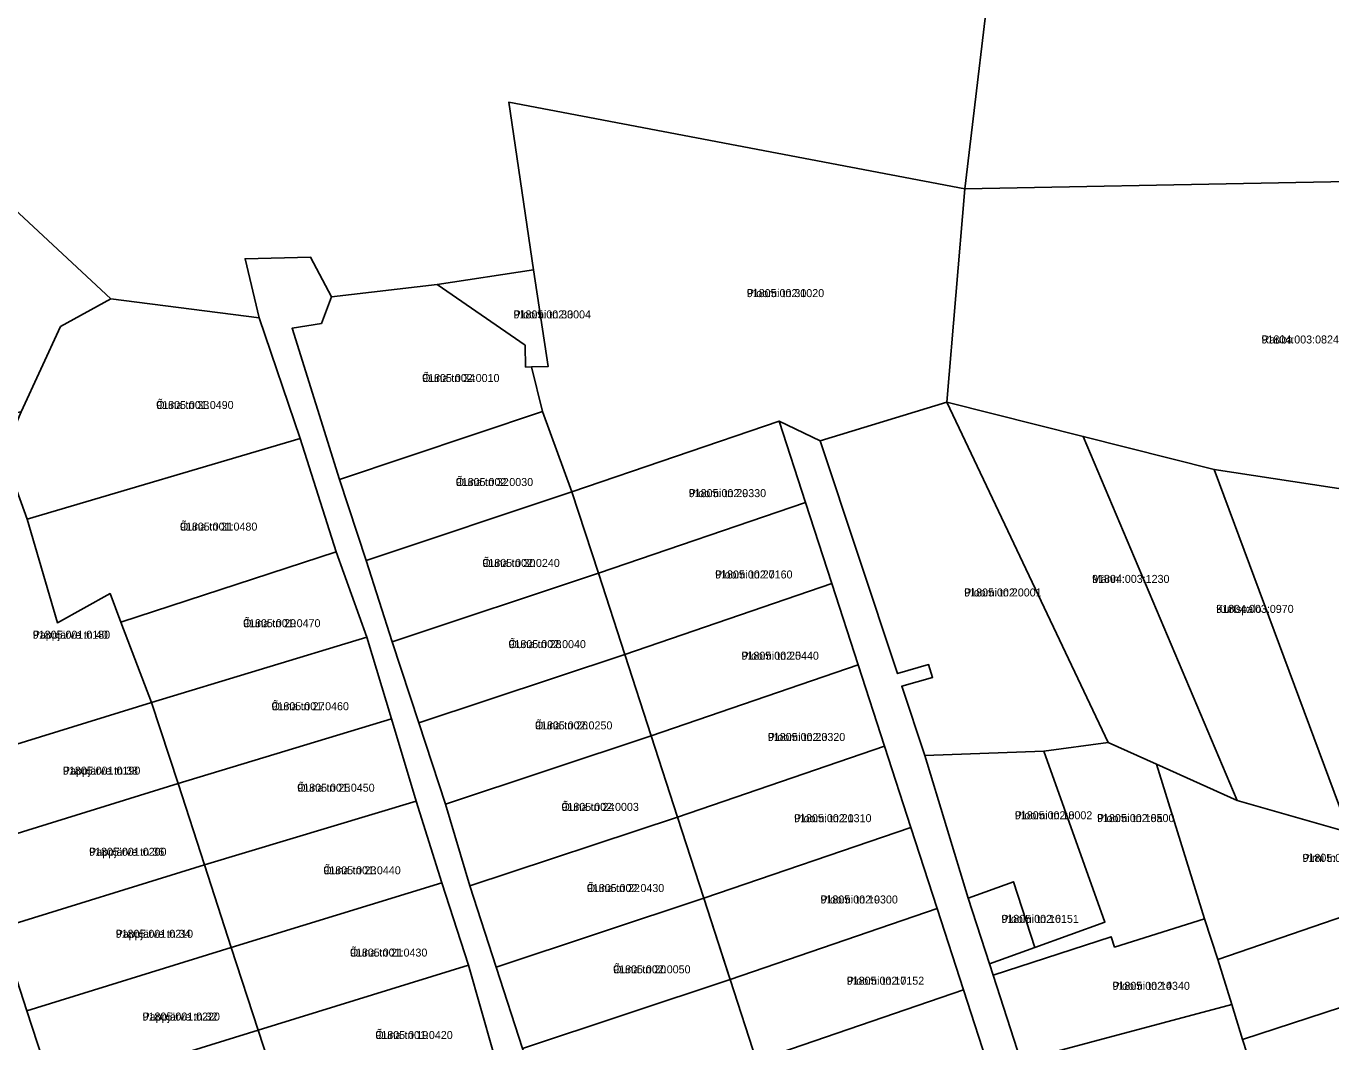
# Model space of a CAD drawing. Extents: x 655954 to 711923, y 6395079 to 6429745.
# Drawn here: x 680310.1 to 680554.7, y 6412480.8 to 6412671.1 of the extents above; entities that cross this region are included whole.
import ezdxf

# ---------------------------------------------------------------- set-up
doc = ezdxf.new("R2010")
doc.units = 0
for name, color, linetype in [('L_AADRESS', 7, 'Continuous'), ('PIIR', 7, 'Continuous'), ('TUNNUS', 7, 'Continuous')]:
    doc.layers.add(name, color=color, linetype=linetype)

msp = doc.modelspace()

# ---------------------------------------------------------------- linework, layer by layer
at = {"layer": 'PIIR'}
for points in [[(680073.18, 6412716.55), (679963.62, 6412773.02), (680013.99, 6412769.75), (680328.3, 6412722.25), (680332.79, 6412721.57), (680343.95, 6412719.89), (680491.74, 6412688.36), (680486.09, 6412640.6), (680400.58, 6412656.82), (680405.26, 6412625.45), (680387.19, 6412622.66), (680367.38, 6412620.4), (680363.46, 6412627.78), (680351.17, 6412627.52), (680353.8, 6412616.41), (680326.05, 6412620), (680257.17, 6412684.06), (680249.09, 6412691.57), (680191.97, 6412698), (680185.92, 6412698.62), (680079.1, 6412709.57)], [(680079.1, 6412709.57), (680185.92, 6412698.62), (680191.97, 6412698), (680249.09, 6412691.57), (680257.17, 6412684.06), (680326.05, 6412620), (680316.57, 6412614.8), (680309.19, 6412598.8), (680270.74, 6412592.3), (680233.25, 6412591.29), (680181.76, 6412579.27), (680138.22, 6412633.47), (680079.96, 6412707.89)], [(680491.74, 6412688.36), (680636.79, 6412656.6), (680647.63, 6412619.14), (680657.8, 6412581.77), (680595.75, 6412580.4), (680603.61, 6412642.87), (680486.09, 6412640.6)], [(680406.92, 6412598.88), (680404.87, 6412607.28), (680407.96, 6412607.31), (680405.26, 6412625.45), (680400.58, 6412656.82), (680486.09, 6412640.6), (680482.71, 6412600.64), (680458.97, 6412593.42), (680451.28, 6412597.1), (680412.42, 6412583.82)], [(680603.61, 6412642.87), (680595.75, 6412580.4), (680579.88, 6412580.85), (680532.8, 6412588.04), (680508.26, 6412594.22), (680482.71, 6412600.64), (680486.09, 6412640.6)], [(680387.19, 6412622.66), (680405.26, 6412625.45), (680407.96, 6412607.31), (680404.87, 6412607.28), (680403.74, 6412607.21), (680403.66, 6412611.31)], [(680359.99, 6412614.49), (680365.49, 6412615.4), (680367.38, 6412620.4), (680387.19, 6412622.66), (680403.66, 6412611.31), (680403.74, 6412607.21), (680404.87, 6412607.28), (680406.92, 6412598.88), (680368.89, 6412586.16)], [(680316.57, 6412614.8), (680326.05, 6412620), (680353.8, 6412616.41), (680361.49, 6412593.83), (680310.35, 6412578.72), (680305.94, 6412590.99), (680309.19, 6412598.8)], [(680482.71, 6412600.64), (680512.94, 6412536.85), (680500.84, 6412535.21), (680478.56, 6412534.41), (680474.24, 6412547.4), (680480.01, 6412549.05), (680479.27, 6412551.45), (680473.46, 6412549.78), (680458.97, 6412593.42)], [(680537.12, 6412526), (680521.99, 6412532.79), (680512.94, 6412536.85), (680482.71, 6412600.64), (680508.26, 6412594.22)], [(680373.9, 6412570.97), (680368.89, 6412586.16), (680406.92, 6412598.88), (680412.42, 6412583.82)], [(680451.28, 6412597.1), (680456.21, 6412581.86), (680417.39, 6412568.58), (680412.42, 6412583.82)], [(680325.88, 6412564.76), (680316, 6412559.3), (680310.35, 6412578.72), (680361.49, 6412593.83), (680368.25, 6412572.56), (680327.92, 6412559.41)], [(680558.11, 6412520.02), (680537.12, 6412526), (680508.26, 6412594.22), (680532.8, 6412588.04)], [(680305.94, 6412590.99), (680310.35, 6412578.72), (680316, 6412559.3), (680325.88, 6412564.76), (680327.92, 6412559.41), (680333.63, 6412544.38), (680295.42, 6412532.55), (680289.16, 6412551.54)], [(680579.88, 6412580.85), (680605.86, 6412505.28), (680576.12, 6412514.47), (680570.21, 6412516.3), (680558.11, 6412520.02), (680532.8, 6412588.04)], [(680378.76, 6412555.7), (680373.9, 6412570.97), (680412.42, 6412583.82), (680417.39, 6412568.58)], [(680456.21, 6412581.86), (680461.14, 6412566.64), (680422.35, 6412553.34), (680417.39, 6412568.58)], [(680368.25, 6412572.56), (680374, 6412556.63), (680333.63, 6412544.38), (680327.92, 6412559.41)], [(680378.76, 6412555.7), (680417.39, 6412568.58), (680422.35, 6412553.34), (680383.72, 6412540.52)], [(680461.14, 6412566.64), (680466.07, 6412551.41), (680427.29, 6412538.12), (680422.35, 6412553.34)], [(680374, 6412556.63), (680378.64, 6412541.32), (680338.67, 6412529.2), (680333.63, 6412544.38)], [(680383.72, 6412540.52), (680422.35, 6412553.34), (680427.29, 6412538.12), (680388.72, 6412525.31)], [(680466.07, 6412551.41), (680471.01, 6412536.19), (680432.22, 6412522.89), (680427.29, 6412538.12)], [(680333.63, 6412544.38), (680338.67, 6412529.2), (680300.34, 6412517.31), (680295.42, 6412532.55)], [(680378.64, 6412541.32), (680383.27, 6412525.9), (680343.58, 6412513.96), (680338.67, 6412529.2)], [(680427.29, 6412538.12), (680432.22, 6412522.89), (680393.31, 6412509.98), (680388.72, 6412525.31)], [(680471.01, 6412536.19), (680475.93, 6412520.96), (680437.15, 6412507.67), (680432.22, 6412522.89)], [(680490.68, 6412495.36), (680499.16, 6412498.42), (680512.32, 6412503.2), (680500.84, 6412535.21), (680512.94, 6412536.85), (680521.99, 6412532.79), (680530.99, 6412503.84), (680514.14, 6412498.52), (680513.5, 6412500.46), (680491.36, 6412493.27)], [(680478.56, 6412534.41), (680500.84, 6412535.21), (680512.32, 6412503.2), (680499.16, 6412498.42), (680495.17, 6412510.78), (680486.69, 6412507.71)], [(680533.46, 6412496.2), (680530.99, 6412503.84), (680521.99, 6412532.79), (680537.12, 6412526), (680558.11, 6412520.02), (680570.21, 6412516.3), (680573.07, 6412509.81)], [(680338.67, 6412529.2), (680343.58, 6412513.96), (680305.26, 6412502.08), (680300.34, 6412517.31)], [(680343.58, 6412513.96), (680383.27, 6412525.9), (680388.05, 6412510.55), (680348.59, 6412498.45)], [(680393.31, 6412509.98), (680432.22, 6412522.89), (680437.15, 6412507.67), (680398.24, 6412494.78)], [(680475.93, 6412520.96), (680480.87, 6412505.74), (680442.08, 6412492.44), (680437.15, 6412507.67)], [(680343.58, 6412513.96), (680348.59, 6412498.45), (680310.3, 6412486.58), (680305.26, 6412502.08)], [(680348.59, 6412498.45), (680388.05, 6412510.55), (680393.05, 6412495.15), (680353.64, 6412482.95)], [(680486.69, 6412507.71), (680495.17, 6412510.78), (680499.16, 6412498.42), (680490.68, 6412495.36)], [(680538.11, 6412481.23), (680536.07, 6412487.8), (680533.46, 6412496.2), (680573.07, 6412509.81), (680578.1, 6412494.24)], [(680398.24, 6412494.78), (680437.15, 6412507.67), (680441.72, 6412493.55), (680442.08, 6412492.44), (680403.17, 6412479.55)], [(680480.87, 6412505.74), (680485.79, 6412490.52), (680447.01, 6412477.21), (680442.08, 6412492.44)], [(680496.53, 6412477.2), (680491.36, 6412493.27), (680513.5, 6412500.46), (680514.14, 6412498.52), (680530.99, 6412503.84), (680533.46, 6412496.2), (680536.07, 6412487.8)], [(680348.59, 6412498.45), (680353.64, 6412482.95), (680315.35, 6412471.08), (680310.3, 6412486.58)], [(680353.64, 6412482.95), (680393.05, 6412495.15), (680397.69, 6412478.89), (680358.69, 6412467.45)], [(680403.17, 6412479.55), (680442.08, 6412492.44), (680447.01, 6412477.21), (680408.11, 6412464.32)], [(680543, 6412466), (680540.64, 6412473.35), (680538.11, 6412481.23), (680578.1, 6412494.24), (680582.92, 6412478.99)], [(680485.79, 6412490.52), (680490.73, 6412475.29), (680452.04, 6412461.99), (680447.01, 6412477.21)], [(680501.58, 6412461.01), (680496.53, 6412477.2), (680536.07, 6412487.8), (680538.11, 6412481.23), (680540.64, 6412473.35)], [(680353.64, 6412482.95), (680358.69, 6412467.45), (680320.4, 6412455.58), (680320.31, 6412455.85), (680315.35, 6412471.08)]]:
    msp.add_lwpolyline(points, close=True, dxfattribs=at)
for points in [[(680397.69, 6412478.89), (680393.05, 6412495.15), (680388.05, 6412510.55), (680383.27, 6412525.9), (680378.64, 6412541.32), (680374, 6412556.63), (680368.25, 6412572.56), (680361.49, 6412593.83), (680353.8, 6412616.41), (680351.17, 6412627.52), (680363.46, 6412627.78), (680367.38, 6412620.4), (680365.49, 6412615.4), (680359.99, 6412614.49), (680368.89, 6412586.16), (680373.9, 6412570.97), (680378.76, 6412555.7), (680383.72, 6412540.52), (680388.72, 6412525.31), (680393.31, 6412509.98), (680398.24, 6412494.78), (680403.17, 6412479.55)], [(680490.73, 6412475.29), (680485.79, 6412490.52), (680480.87, 6412505.74), (680475.93, 6412520.96), (680471.01, 6412536.19), (680466.07, 6412551.41), (680461.14, 6412566.64), (680456.21, 6412581.86), (680451.28, 6412597.1), (680458.97, 6412593.42), (680473.46, 6412549.78), (680479.27, 6412551.45), (680480.01, 6412549.05), (680474.24, 6412547.4), (680478.56, 6412534.41), (680486.69, 6412507.71), (680490.68, 6412495.36), (680491.36, 6412493.27), (680496.53, 6412477.2)], [(680305.26, 6412502.08), (680310.3, 6412486.58), (680315.35, 6412471.08), (680320.31, 6412455.85), (680320.4, 6412455.58), (680325.45, 6412440.08), (680330.5, 6412424.58), (680335.45, 6412409.36), (680335.54, 6412409.08), (680340.5, 6412393.86), (680340.59, 6412393.58), (680345.64, 6412378.08), (680350.69, 6412362.58), (680355.73, 6412347.08), (680360.78, 6412331.58), (680366.09, 6412315.05), (680368.93, 6412304.18), (680371.34, 6412297.19), (680372.55, 6412294.06), (680377.69, 6412279.06)]]:
    msp.add_lwpolyline(points, dxfattribs=at)

# ---------------------------------------------------------------- texts
at = {"layer": 'L_AADRESS'}
for s, p in [('Ploomi tn 31', (680445.2, 6412620.32)), ('Ploomi tn 33', (680401.5, 6412616.33)), ('Rauba', (680541.66, 6412611.63)), ('Õuna tn 34', (680384.36, 6412604.41)), ('Õuna tn 33', (680334.53, 6412599.36)), ('Õuna tn 32', (680390.66, 6412584.92)), ('Ploomi tn 29', (680434.32, 6412582.84)), ('Õuna tn 31', (680338.98, 6412576.57)), ('Õuna tn 30', (680395.65, 6412569.76)), ('Ploomi tn 27', (680439.27, 6412567.6)), ('Männi', (680509.91, 6412566.77)), ('Ploomi tn 20', (680485.95, 6412564.23)), ('Õuna tn 29', (680350.81, 6412558.47)), ('Kurtspalo', (680533.18, 6412561.15)), ('Pappjärve tn 40', (680311.39, 6412556.31)), ('Õuna tn 28', (680400.55, 6412554.55)), ('Ploomi tn 25', (680444.21, 6412552.38)), ('Õuna tn 27', (680356.14, 6412542.91)), ('Õuna tn 26', (680405.51, 6412539.32)), ('Ploomi tn 23', (680449.15, 6412537.15)), ('Pappjärve tn 38', (680317.05, 6412530.84)), ('Õuna tn 25', (680360.96, 6412527.64)), ('Õuna tn 24', (680410.47, 6412524.05)), ('Ploomi tn 18', (680495.44, 6412522.48)), ('Ploomi tn 21', (680454.07, 6412521.93)), ('Ploomi tn 18a', (680510.84, 6412521.95)), ('Pappjärve tn 36', (680321.96, 6412515.64)), ('Õuna tn 23', (680365.85, 6412512.17)), ('Pirni tn 13', (680549.34, 6412514.49)), ('Õuna tn 22', (680415.23, 6412508.84)), ('Ploomi tn 19', (680459.01, 6412506.7)), ('Ploomi tn 16', (680492.92, 6412503.07)), ('Pappjärve tn 34', (680326.93, 6412500.27)), ('Õuna tn 21', (680370.84, 6412496.75)), ('Õuna tn 20', (680420.16, 6412493.61)), ('Ploomi tn 17', (680463.94, 6412491.48)), ('Ploomi tn 14', (680513.73, 6412490.52)), ('Pappjärve tn 32', (680331.97, 6412484.76)), ('Õuna tn 19', (680375.59, 6412481.3))]:
    msp.add_text(s, height=1.5, dxfattribs=at).set_placement(p)
at = {"layer": 'TUNNUS'}
for s, p in [('91805:002:0020', (680445.2, 6412620.32)), ('91805:002:0004', (680401.5, 6412616.33)), ('91804:003:0824', (680541.66, 6412611.63)), ('91805:002:0010', (680384.36, 6412604.41)), ('91805:001:0490', (680334.53, 6412599.36)), ('91805:002:0030', (680390.66, 6412584.92)), ('91805:002:0330', (680434.32, 6412582.84)), ('91805:001:0480', (680338.98, 6412576.57)), ('91805:002:0240', (680395.65, 6412569.76)), ('91805:002:0160', (680439.27, 6412567.6)), ('91804:003:1230', (680509.91, 6412566.77)), ('91805:002:0001', (680485.95, 6412564.23)), ('91804:003:0970', (680533.18, 6412561.15)), ('91805:001:0470', (680350.81, 6412558.47)), ('91805:001:0180', (680311.39, 6412556.31)), ('91805:002:0040', (680400.55, 6412554.55)), ('91805:002:0440', (680444.21, 6412552.38)), ('91805:001:0460', (680356.14, 6412542.91)), ('91805:002:0250', (680405.51, 6412539.32)), ('91805:002:0320', (680449.15, 6412537.15)), ('91805:001:0190', (680317.05, 6412530.84)), ('91805:001:0450', (680360.96, 6412527.64)), ('91805:002:0003', (680410.47, 6412524.05)), ('91805:002:0002', (680495.44, 6412522.48)), ('91805:002:0310', (680454.07, 6412521.93)), ('91805:002:0500', (680510.84, 6412521.95)), ('91805:001:0200', (680321.96, 6412515.64)), ('91805:002:0230', (680549.34, 6412514.49)), ('91805:001:0440', (680365.85, 6412512.17)), ('91805:002:0430', (680415.23, 6412508.84)), ('91805:002:0300', (680459.01, 6412506.7)), ('91805:002:0151', (680492.92, 6412503.07)), ('91805:001:0210', (680326.93, 6412500.27)), ('91805:001:0430', (680370.84, 6412496.75)), ('91805:002:0050', (680420.16, 6412493.61)), ('91805:002:0152', (680463.94, 6412491.48)), ('91805:002:0340', (680513.73, 6412490.52)), ('91805:001:0220', (680331.97, 6412484.76)), ('91805:001:0420', (680375.59, 6412481.3))]:
    msp.add_text(s, height=1.5, dxfattribs=at).set_placement(p)

doc.saveas('drawing.dxf')
